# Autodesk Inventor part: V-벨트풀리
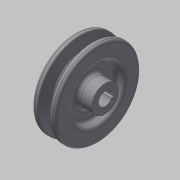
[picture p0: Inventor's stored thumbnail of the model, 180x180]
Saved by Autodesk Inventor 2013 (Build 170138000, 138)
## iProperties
Created: 2015-02
Part Number: V-벨트풀리
Material: 일반
Document SubType Name: Modeling
Designer: Administrator
Density: 1 g/cm^3
Author: Administrator
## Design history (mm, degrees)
sketch "스케치1"
  geometry: L1 (-12.5, 0)-(12.5, 0); L2 (12.5, 5.5)-(-12.5, 5.5); L3 (-12.5, 5.5)-(-12.5, 11); L4 (-12.5, 21.5)-(-6.5, 21.5); L5 (-6.5, 21.5)-(-6.5, 11); L6 (-6.5, 11)-(-12.5, 11); L7 (6.5, 21.5)-(0.5, 21.5); L8 (0.5, 21.5)-(0.5, 11); L9 (12.5, 5.5)-(12.5, 11); L10 (12.5, 11)-(0.5, 11); L11 (-7, 32.5)-(1, 32.5); L12 (-12.5, 21.5)-(-12.5, 35.2); L13 (-12.5, 35.2)-(-7.825, 35.2); L14 (-7.825, 35.2)-(-5.074, 26.2); L15 (-5.074, 26.2)-(-0.926, 26.2); L16 (-0.926, 26.2)-(1.825, 35.2); L17 (1.825, 35.2)-(6.5, 35.2); L18 (6.5, 35.2)-(6.5, 21.5); 3 further points
  constraints: 36 end point, 7 perpendicular, 5 parallel, 2 equal length, 2 midpoint, 2 point on line, 2 vertical alignment, 1 coincident, 1 collinear, 1 horizontal
  dimensions: "d0" = 25 distance of L1.start L1.end; "d19" = 11 diameter of L2 L1; "d21" = 43 diameter of L7 L1; "d22" = 43 diameter of L4 L1; "d25" = 22 diameter of L10 L1; "d26" = 22 diameter of L6 L1; "d27" = 6 distance of L7.start L7.end; "d30" = 6 distance of L4.start L4.end; "d31" = 65 diameter of L11 L1; "d32" = 8 distance of L11.end L11.start; "d33" = 34 deg angle of L16 L14; "d34" = 19 distance between parallel lines of L18 L12; "d35" = 25 distance between parallel lines of L9 L12; "d36" = 6.3 distance between parallel lines of L11 L15; "d37" = 2.7 distance between parallel lines of L11 L17
revolve "회전1" sketch "스케치1" stored, may be unused: angle "d13" = 90 deg
sketch "스케치2"
  geometry: L1 (-2, 5.123)-(-2, 7.3); L2 (-2, 7.3)-(2, 7.3); L3 (2, 7.3)-(2, 5.123); C1 r 11 at (0, 0) reference; A1 r 5.5 centre (0, 0) between (-2, 5.123) and (2, 5.123); 2 further points
  constraints: 6 end point, 2 point on circle, 1 centre point, 1 coincident, 1 midpoint, 1 parallel, 1 perpendicular, 1 vertical, 1 vertical alignment, 3 other
  dimensions: "d38" = 4 distance of L1.end L2.end; "d40" = 7.3 distance from line of L2 point (0, 0)
extrude "돌출1" cut sketch "스케치2" stored distance "d41" = 10; taper "d42" = 0 deg
fillet "모깎기1" dims "d43" = 3
fillet "모깎기2" dims "d44" = 3
fillet "모깎기3" dims "d45" = 1
fillet "모깎기4" dims "d46" = 0.5
fillet "모깎기5" dims "d47" = 2
fillet "모깎기6" dims "d48" = 3
fillet "모깎기7" dims "d49" = 3
node "솔리드1"
